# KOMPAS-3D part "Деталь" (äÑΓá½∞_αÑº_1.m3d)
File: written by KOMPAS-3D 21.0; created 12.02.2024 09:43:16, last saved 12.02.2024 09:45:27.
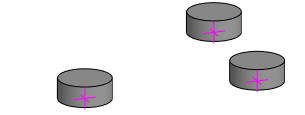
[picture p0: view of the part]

Document properties: Автор: alg; Полное имя файла: C:\Деталь_рез_1.m3d

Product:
- Part/product: Деталь

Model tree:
1. Эскиз:2
2. Тело без истории:1
3. Тело без истории:2
4. Тело без истории:3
